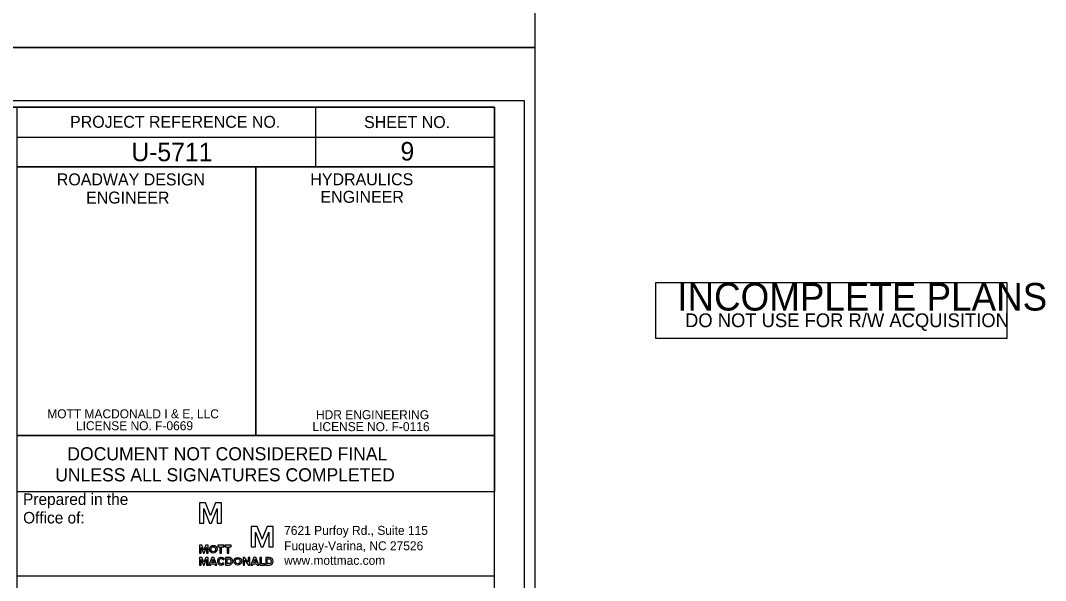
# Model space of a CAD drawing. Extents: x 1754992 to 1757273, y 732111 to 735411.
# Drawn here: x 1756649.1 to 1757078.4, y 734087.6 to 734322 of the extents above; entities that cross this region are included whole.
import ezdxf

# ---------------------------------------------------------------- set-up
doc = ezdxf.new("R2010")
doc.units = 0
for name, color, linetype in [('Old_Level_2', 7, 'Continuous'), ('Old_Level_3', 7, 'Continuous'), ('Old_Level_42', 7, 'Continuous'), ('Old_Level_45', 7, 'Continuous'), ('Sheet Cutting Line CELL', 7, 'Continuous'), ('Sheet Data Field CELL', 7, 'Continuous'), ('Sheet Plot Border Inside CELL', 7, 'Continuous'), ('Sheet Plot Border Outside CELL', 7, 'Continuous'), ('Sheet Profile CELL', 7, 'Continuous'), ('Sheet Profile Grid Major CELL', 7, 'Continuous'), ('Sheet Profile Grid Minor CELL', 7, 'Continuous'), ('Sheet Sticker Exception Certification CELL', 7, 'Continuous'), ('Sheet Sticker Incomplete CELL', 7, 'Continuous')]:
    doc.layers.add(name, color=color, linetype=linetype)

msp = doc.modelspace()

# ---------------------------------------------------------------- linework, layer by layer
at = {"layer": 'Old_Level_2'}
for p, q in [((1756726.6, 734120.13), (1756724.08, 734120.13)), ((1756724.08, 734120.13), (1756724.08, 734111.63)), ((1756728.65, 734114.88), (1756726.6, 734120.13)), ((1756730.76, 734120.13), (1756728.71, 734114.88)), ((1756733.28, 734120.13), (1756730.76, 734120.13)), ((1756733.28, 734111.63), (1756733.28, 734120.13)), ((1756725.87, 734111.63), (1756725.87, 734117.74)), ((1756725.87, 734117.74), (1756725.9, 734117.74)), ((1756725.9, 734117.74), (1756728.29, 734111.63)), ((1756729.07, 734111.63), (1756731.46, 734117.77)), ((1756731.46, 734117.77), (1756731.49, 734117.77)), ((1756731.49, 734117.77), (1756731.49, 734111.63)), ((1756724.08, 734111.63), (1756725.87, 734111.63)), ((1756728.29, 734111.63), (1756729.07, 734111.63)), ((1756728.65, 734114.8), (1756728.65, 734114.88)), ((1756728.71, 734114.8), (1756728.65, 734114.8)), ((1756728.71, 734114.88), (1756728.71, 734114.8)), ((1756731.49, 734111.63), (1756733.28, 734111.63)), ((1756748.21, 734110.23), (1756745.69, 734110.23)), ((1756745.69, 734110.23), (1756745.69, 734101.73)), ((1756747.49, 734101.73), (1756747.49, 734107.84)), ((1756747.49, 734107.84), (1756747.51, 734107.84)), ((1756747.51, 734107.84), (1756749.9, 734101.73)), ((1756750.27, 734104.98), (1756748.21, 734110.23)), ((1756752.37, 734110.23), (1756750.32, 734104.98)), ((1756750.68, 734101.73), (1756753.08, 734107.86)), ((1756754.9, 734110.23), (1756752.37, 734110.23)), ((1756753.08, 734107.86), (1756753.1, 734107.86)), ((1756753.1, 734107.86), (1756753.1, 734101.73)), ((1756754.9, 734101.73), (1756754.9, 734110.23)), ((1756725.04, 734102.33), (1756724.08, 734102.33)), ((1756724.08, 734102.33), (1756724.08, 734099.08)), ((1756725.85, 734100.3), (1756725.04, 734102.33)), ((1756726.65, 734102.33), (1756725.85, 734100.3)), ((1756727.61, 734102.33), (1756726.65, 734102.33)), ((1756727.61, 734099.08), (1756727.61, 734102.33)), ((1756727.61, 734099.08), (1756727.61, 734102.33)), ((1756750.27, 734104.9), (1756750.27, 734104.98)), ((1756750.32, 734104.9), (1756750.27, 734104.9)), ((1756750.32, 734104.98), (1756750.32, 734104.9)), ((1756724.08, 734099.08), (1756724.75, 734099.08)), ((1756724.75, 734099.08), (1756724.75, 734101.42)), ((1756724.75, 734101.42), (1756724.78, 734101.42)), ((1756724.75, 734101.42), (1756724.78, 734101.42)), ((1756724.78, 734101.42), (1756725.69, 734099.08)), ((1756725.69, 734099.08), (1756726, 734099.08)), ((1756726, 734099.08), (1756726.91, 734101.42)), ((1756726.91, 734101.42), (1756726.94, 734101.42)), ((1756726.91, 734101.42), (1756726.94, 734101.42)), ((1756726.91, 734101.42), (1756726.94, 734101.42)), ((1756726.94, 734101.42), (1756726.94, 734099.08)), ((1756726.94, 734099.08), (1756727.61, 734099.08)), ((1756745.69, 734101.73), (1756747.49, 734101.73)), ((1756749.9, 734101.73), (1756750.68, 734101.73)), ((1756753.1, 734101.73), (1756754.9, 734101.73)), ((1756725.04, 734097.28), (1756724.08, 734097.28)), ((1756724.08, 734097.28), (1756724.08, 734094.03)), ((1756724.08, 734094.03), (1756724.75, 734094.03)), ((1756724.75, 734094.03), (1756724.75, 734096.37)), ((1756724.75, 734096.37), (1756724.78, 734096.37)), ((1756724.78, 734096.37), (1756725.69, 734094.03)), ((1756725.85, 734095.25), (1756725.04, 734097.28)), ((1756725.69, 734094.03), (1756726, 734094.03)), ((1756726.65, 734097.28), (1756725.85, 734095.25)), ((1756726, 734094.03), (1756726.91, 734096.37)), ((1756727.61, 734097.28), (1756726.65, 734097.28)), ((1756726.91, 734096.37), (1756726.94, 734096.37)), ((1756726.94, 734096.37), (1756726.94, 734094.03)), ((1756726.94, 734094.03), (1756727.61, 734094.03)), ((1756727.61, 734094.03), (1756727.61, 734097.28)), ((1756734.44, 734094.7), (1756733.88, 734094.98)), ((1756734.44, 734094.7), (1756733.88, 734094.98)), ((1756733.96, 734096.22), (1756734.52, 734096.49)), ((1756733.96, 734096.22), (1756734.52, 734096.49)), ((1756736.45, 734097.28), (1756734.97, 734097.28)), ((1756734.97, 734097.28), (1756734.97, 734095.6)), ((1756734.97, 734095.6), (1756734.97, 734094.03)), ((1756734.97, 734094.03), (1756736.45, 734094.03)), ((1756735.65, 734094.66), (1756735.65, 734096.68)), ((1756735.65, 734096.68), (1756736.45, 734096.68)), ((1756736.45, 734094.66), (1756735.65, 734094.66)), ((1756751.79, 734097.28), (1756751.79, 734097.28)), ((1756753.27, 734097.28), (1756751.79, 734097.28)), ((1756751.79, 734097.28), (1756751.79, 734095.6)), ((1756751.79, 734095.6), (1756751.79, 734094.03)), ((1756751.79, 734094.03), (1756753.27, 734094.03)), ((1756752.46, 734094.66), (1756752.46, 734096.68)), ((1756752.46, 734096.68), (1756753.27, 734096.68)), ((1756753.27, 734094.66), (1756752.46, 734094.66)), ((1756753.27, 734096.66), (1756753.27, 734096.66))]:
    msp.add_line(p, q, dxfattribs=at)
for points in [[(1756731.69, 734101.73), (1756732.63, 734101.73), (1756732.63, 734099.08), (1756733.33, 734099.08), (1756733.33, 734101.73), (1756734.27, 734101.73), (1756734.27, 734102.33), (1756731.69, 734102.33), (1756731.69, 734101.73)], [(1756734.68, 734101.73), (1756735.62, 734101.73), (1756735.62, 734099.08), (1756736.32, 734099.08), (1756736.32, 734101.73), (1756737.26, 734101.73), (1756737.26, 734102.33), (1756734.68, 734102.33), (1756734.68, 734101.73)], [(1756728, 734094.03), (1756728.78, 734094.03), (1756728.99, 734094.58), (1756730.4, 734094.58), (1756730.6, 734094.03), (1756731.36, 734094.03), (1756730.11, 734097.28), (1756729.25, 734097.28), (1756728, 734094.03)], [(1756729.17, 734095.18), (1756729.69, 734096.58), (1756730.21, 734095.18), (1756729.17, 734095.18)], [(1756742.92, 734096.14), (1756742.95, 734096.14), (1756744.51, 734094.03), (1756745.16, 734094.03), (1756745.16, 734097.28), (1756744.48, 734097.28), (1756744.48, 734095.23), (1756742.95, 734097.28), (1756742.27, 734097.28), (1756742.27, 734094.03), (1756742.92, 734094.03), (1756742.92, 734096.14)], [(1756745.58, 734094.03), (1756746.35, 734094.03), (1756746.56, 734094.58), (1756747.97, 734094.58), (1756748.17, 734094.03), (1756748.93, 734094.03), (1756747.68, 734097.28), (1756746.82, 734097.28), (1756745.58, 734094.03)], [(1756746.75, 734095.18), (1756747.27, 734096.58), (1756747.79, 734095.18), (1756746.75, 734095.18)], [(1756751.4, 734094.03), (1756751.4, 734094.61), (1756749.99, 734094.61), (1756749.99, 734097.28), (1756749.32, 734097.28), (1756749.32, 734094.03), (1756751.4, 734094.03)], [(1756751.4, 734094.03), (1756751.4, 734094.61), (1756749.99, 734094.61), (1756749.99, 734097.28), (1756749.32, 734097.28), (1756749.32, 734094.03), (1756751.4, 734094.04), (1756751.4, 734094.61)]]:
    msp.add_lwpolyline(points, dxfattribs=at)
msp.add_arc((1756753.27, 734095.66), 1.62, 270, 90, dxfattribs=at)
for centre, major_axis, ratio in [((1756729.82, 734100.7), (0, 1.62), 0.993118), ((1756729.82, 734100.7), (0, 1.06), 0.916103), ((1756740.09, 734095.66), (0, 1.62), 0.993118), ((1756740.09, 734095.66), (0, 1.06), 0.916103)]:
    msp.add_ellipse(centre, major_axis=major_axis, ratio=ratio, dxfattribs=at)
for centre, major_axis, ratio, start_param, end_param in [((1756733.14, 734095.66), (0, 1.62), 0.993118, 5.246647, 10.366427), ((1756733.14, 734095.66), (0, 1.62), 0.993118, 5.246647, 10.366427), ((1756733.14, 734095.66), (0, 1.06), 0.916103, 5.276876, 9.424778), ((1756733.14, 734095.66), (0, 1.06), 0.916103, 5.276876, 10.296021), ((1756733.14, 734095.66), (0, 1.06), 0.916103, 3.141593, 4.012835), ((1756736.45, 734095.66), (0, -1.62), 0.930276, 0, 3.141593), ((1756736.45, 734095.67), (0, -1.01), 0.900832, 0, 3.141593), ((1756753.27, 734095.67), (0, -1.01), 0.900832, 0, 3.141593)]:
    msp.add_ellipse(centre, major_axis=major_axis, ratio=ratio, start_param=start_param, end_param=end_param, dxfattribs=at)
at = {"layer": 'Old_Level_42'}
msp.add_lwpolyline([(1756847.67, 734089.43), (1756647.62, 734089.43), (1756647.62, 734124.73)], dxfattribs=at)
at = {"layer": 'Sheet Cutting Line CELL'}
for p, q in [((1755180.67, 734310.78), (1756864.67, 734310.78)), ((1756864.67, 734310.78), (1755180.67, 734310.78))]:
    msp.add_line(p, q, dxfattribs=at)
at = {"layer": 'Sheet Plot Border Inside CELL'}
msp.add_lwpolyline([(1755193.67, 733233.23), (1756860.17, 733233.23), (1756860.17, 734288.33), (1755193.67, 734288.33)], close=True, dxfattribs=at)
at = {"layer": 'Sheet Plot Border Outside CELL'}
for points in [[(1755180.67, 734310.78), (1756864.67, 734310.78), (1756864.67, 735410.78), (1755180.67, 735410.78)], [(1755180.67, 733210.78), (1756864.67, 733210.78), (1756864.67, 734310.78), (1755180.67, 734310.78)]]:
    msp.add_lwpolyline(points, close=True, dxfattribs=at)
at = {"layer": 'Sheet Profile CELL'}
for p, q in [((1756772.67, 734285.73), (1756772.67, 734260.73)), ((1756647.62, 734273.23), (1756847.67, 734273.23)), ((1756747.67, 734260.73), (1756747.67, 734148.28))]:
    msp.add_line(p, q, dxfattribs=at)
for points in [[(1756847.67, 734285.78), (1755347.67, 734285.78), (1755347.67, 733235.78), (1756847.67, 733235.78)], [(1756647.62, 734285.78), (1756847.67, 734285.78), (1756847.67, 734260.73), (1756647.62, 734260.73)], [(1756647.62, 734260.73), (1756747.67, 734260.73), (1756747.67, 734148.23), (1756647.62, 734148.23)], [(1756747.67, 734260.73), (1756847.67, 734260.73), (1756847.67, 734148.23), (1756747.67, 734148.23)]]:
    msp.add_lwpolyline(points, close=True, dxfattribs=at)
at = {"layer": 'Sheet Profile Grid Major CELL'}
for points in [[(1756097.67, 733785.78), (1756147.67, 733785.78), (1756147.67, 734285.78), (1756197.67, 734285.78), (1756197.67, 733785.78), (1756247.67, 733785.78), (1756247.67, 734285.78), (1756297.67, 734285.78), (1756297.67, 733785.78), (1756347.67, 733785.78), (1756347.67, 734285.78), (1756397.67, 734285.78), (1756397.67, 733785.78), (1756447.67, 733785.78), (1756447.67, 734285.78), (1756497.67, 734285.78), (1756497.67, 733785.78), (1756547.67, 733785.78), (1756547.67, 734285.78), (1756597.67, 734285.78), (1756597.67, 733785.78), (1756647.67, 733785.78), (1756647.67, 734285.78), (1756673.97, 734285.78)], [(1756797.67, 734052.66), (1756797.67, 733785.78), (1756847.67, 733785.78), (1756847.67, 734135.78)]]:
    msp.add_lwpolyline(points, dxfattribs=at)
at = {"layer": 'Sheet Profile Grid Minor CELL'}
msp.add_lwpolyline([(1756642.67, 734285.78), (1756652.67, 734285.78)], dxfattribs=at)
at = {"layer": 'Sheet Sticker Exception Certification CELL'}
for p, q in [((1756647.62, 734148.23), (1756847.66, 734148.23)), ((1756647.62, 734148.23), (1756847.66, 734148.23)), ((1756847.66, 734148.22), (1756847.66, 734124.72)), ((1756847.66, 734148.22), (1756847.66, 734124.72)), ((1756847.66, 734124.73), (1756647.62, 734124.73)), ((1756847.66, 734124.73), (1756647.62, 734124.73))]:
    msp.add_line(p, q, dxfattribs=at)
at = {"layer": 'Sheet Sticker Incomplete CELL'}
msp.add_lwpolyline([(1756915.22, 734188.9), (1756915.22, 734212.4), (1757062.22, 734212.4), (1757062.22, 734188.9)], close=True, dxfattribs=at)

# ---------------------------------------------------------------- texts
at = {"layer": 'Old_Level_2'}
for s, height, p in [('Prepared in the ', 4.8186, (1756650.17, 734119.23)), ('Office of:', 4.819, (1756650.17, 734111.48))]:
    msp.add_text(s, height=height, dxfattribs=at).set_placement(p)
for s, p in [('7621 Purfoy Rd., Suite 115', (1756759.5, 734106.71)), ('Fuquay-Varina, NC 27526', (1756759.5, 734100.26)), ('www.mottmac.com', (1756759.5, 734094.17))]:
    msp.add_text(s, height=3.75, rotation=360, dxfattribs=at).set_placement(p)
at = {"layer": 'Old_Level_3'}
for s, p in [('HDR ENGINEERING', (1756772.84, 734155.13)), (' LICENSE NO. F-0116', (1756769.97, 734150.13))]:
    msp.add_text(s, height=3.75, rotation=360, dxfattribs=at).set_placement(p)
at = {"layer": 'Old_Level_45'}
for s, p in [('MOTT MACDONALD I & E, LLC', (1756660.28, 734155.51)), (' LICENSE NO. F-0669', (1756670.91, 734150.51))]:
    msp.add_text(s, height=3.75, rotation=360, dxfattribs=at).set_placement(p)
at = {"layer": 'Sheet Data Field CELL'}
for s, p in [('U-5711', (1756695.48, 734263.1)), ('9', (1756808.23, 734263.4))]:
    msp.add_text(s, height=7.75, dxfattribs=at).set_placement(p)
at = {"layer": 'Sheet Profile CELL'}
for s, height, p in [('PROJECT REFERENCE NO.', 5.0001, (1756669.83, 734277.1)), ('SHEET NO.', 5, (1756792.98, 734277)), ('ROADWAY DESIGN', 5.0001, (1756664.28, 734253)), ('HYDRAULICS', 5, (1756770.48, 734253.05)), ('ENGINEER', 5, (1756676.53, 734245.4)), ('ENGINEER', 5, (1756774.73, 734245.7))]:
    msp.add_text(s, height=height, dxfattribs=at).set_placement(p)
at = {"layer": 'Sheet Sticker Exception Certification CELL'}
for s, p in [('DOCUMENT NOT CONSIDERED FINAL', (1756668.69, 734137.89)), ('DOCUMENT NOT CONSIDERED FINAL', (1756668.69, 734137.89)), ('UNLESS ALL SIGNATURES COMPLETED', (1756663.62, 734129.09)), ('UNLESS ALL SIGNATURES COMPLETED', (1756663.62, 734129.09))]:
    msp.add_text(s, height=5.5, dxfattribs=at).set_placement(p)
at = {"layer": 'Sheet Sticker Incomplete CELL'}
for s, height, p in [('INCOMPLETE PLANS', 11.52, (1756924.17, 734200.6)), ('DO NOT USE FOR R/W ACQUISITION', 5.76, (1756927.42, 734193.65))]:
    msp.add_text(s, height=height, dxfattribs=at).set_placement(p)

doc.saveas('drawing.dxf')
